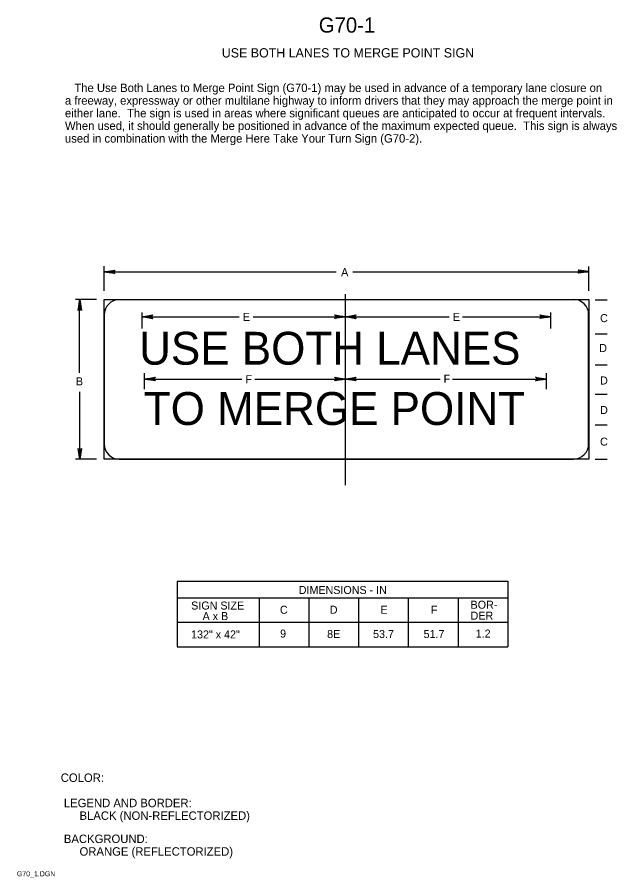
# Model space of a CAD drawing. Extents: x 0.012 to 0.19, y 0.004 to 0.259.
import ezdxf

# ---------------------------------------------------------------- set-up
doc = ezdxf.new("R2010")
doc.units = 0
doc.layers.add('1', color=7, linetype='Continuous')
doc.layers.add('3', color=7, linetype='Continuous')

msp = doc.modelspace()

# ---------------------------------------------------------------- linework, layer by layer
at = {"layer": '1'}
for p, q in [((0.03787, 0.178), (0.03787, 0.18538)), ((0.1815, 0.178), (0.1815, 0.18525)), ((0.03787, 0.18363), (0.10664, 0.18363)), ((0.11156, 0.18365), (0.1815, 0.18365)), ((0.10938, 0.12037), (0.10938, 0.177)), ((0.03563, 0.1755), (0.02938, 0.1755)), ((0.03059, 0.15376), (0.03059, 0.17541)), ((0.03787, 0.12812), (0.03787, 0.1755)), ((0.03787, 0.1755), (0.1815, 0.1755)), ((0.1815, 0.1755), (0.1815, 0.12812)), ((0.18338, 0.17538), (0.187, 0.17538)), ((0.04913, 0.16687), (0.04913, 0.17162)), ((0.10938, 0.16687), (0.10938, 0.17162)), ((0.17025, 0.16687), (0.17025, 0.17162)), ((0.04913, 0.17035), (0.07787, 0.17035)), ((0.082, 0.17037), (0.10938, 0.17037)), ((0.10938, 0.17037), (0.14012, 0.17037)), ((0.14407, 0.17035), (0.17025, 0.17035)), ((0.18338, 0.16525), (0.187, 0.16525)), ((0.18338, 0.15613), (0.187, 0.15613)), ((0.04988, 0.14888), (0.04988, 0.15363)), ((0.10938, 0.14888), (0.10938, 0.15363)), ((0.169, 0.14888), (0.169, 0.15363)), ((0.04988, 0.15187), (0.07867, 0.15187)), ((0.0825, 0.15188), (0.10938, 0.15188)), ((0.10938, 0.15188), (0.1375, 0.15188)), ((0.14118, 0.15187), (0.169, 0.15187)), ((0.03058, 0.14807), (0.03058, 0.12826)), ((0.18338, 0.14738), (0.187, 0.14738)), ((0.18338, 0.13825), (0.187, 0.13825)), ((0.03563, 0.12812), (0.02938, 0.12812)), ((0.1815, 0.12812), (0.03787, 0.12812)), ((0.18338, 0.12812), (0.187, 0.12812))]:
    msp.add_line(p, q, dxfattribs=at)
for points in [[(0.04088, 0.18325), (0.04075, 0.18338), (0.03787, 0.18363), (0.04088, 0.18325), (0.041, 0.18313), (0.03787, 0.18363), (0.04075, 0.18375), (0.04088, 0.18388), (0.03787, 0.18363), (0.041, 0.18413), (0.04088, 0.18388)], [(0.1785, 0.18413), (0.17863, 0.18388), (0.1815, 0.18375), (0.1785, 0.18413), (0.17838, 0.18425), (0.1815, 0.18375), (0.17863, 0.1835), (0.1785, 0.18338), (0.1815, 0.18375), (0.17838, 0.18325), (0.1785, 0.18338)], [(0.03025, 0.1725), (0.0305, 0.17263), (0.03062, 0.1755), (0.03025, 0.1725), (0.03012, 0.17225), (0.03062, 0.1755), (0.03075, 0.17263), (0.031, 0.1725), (0.03062, 0.1755), (0.03112, 0.17225), (0.031, 0.1725)], [(0.05212, 0.17), (0.052, 0.17012), (0.04913, 0.17037), (0.05212, 0.17), (0.05225, 0.16975), (0.04913, 0.17037), (0.052, 0.1705), (0.05212, 0.17062), (0.04913, 0.17037), (0.05225, 0.17087), (0.05212, 0.17062)], [(0.10637, 0.17075), (0.1065, 0.1705), (0.10938, 0.17037), (0.10637, 0.17075), (0.10625, 0.17087), (0.10938, 0.17037), (0.1065, 0.17012), (0.10637, 0.17), (0.10938, 0.17037), (0.10625, 0.16987), (0.10637, 0.17)], [(0.11238, 0.17), (0.11225, 0.17012), (0.10938, 0.17037), (0.11238, 0.17), (0.1125, 0.16975), (0.10938, 0.17037), (0.11225, 0.1705), (0.11238, 0.17062), (0.10938, 0.17037), (0.1125, 0.17087), (0.11238, 0.17062)], [(0.16725, 0.17075), (0.16725, 0.1705), (0.17025, 0.17037), (0.16725, 0.17075), (0.167, 0.17087), (0.17025, 0.17037), (0.16725, 0.17012), (0.16725, 0.17), (0.17025, 0.17037), (0.167, 0.16987), (0.16725, 0.17)], [(0.05287, 0.1515), (0.05275, 0.15175), (0.04988, 0.15188), (0.05287, 0.1515), (0.053, 0.15138), (0.04988, 0.15188), (0.05275, 0.152), (0.05287, 0.15225), (0.04988, 0.15188), (0.053, 0.15238), (0.05287, 0.15225)], [(0.10637, 0.15225), (0.1065, 0.152), (0.10938, 0.15188), (0.10637, 0.15225), (0.10625, 0.15238), (0.10938, 0.15188), (0.1065, 0.15175), (0.10637, 0.1515), (0.10938, 0.15188), (0.10625, 0.15138), (0.10637, 0.1515)], [(0.11238, 0.1515), (0.11225, 0.15175), (0.10938, 0.15188), (0.11238, 0.1515), (0.1125, 0.15138), (0.10938, 0.15188), (0.11225, 0.152), (0.11238, 0.15225), (0.10938, 0.15188), (0.1125, 0.15238), (0.11238, 0.15225)], [(0.166, 0.15225), (0.166, 0.152), (0.169, 0.15188), (0.166, 0.15225), (0.16575, 0.15238), (0.169, 0.15188), (0.166, 0.15175), (0.166, 0.1515), (0.169, 0.15188), (0.16575, 0.15138), (0.166, 0.1515)], [(0.031, 0.13112), (0.03075, 0.131), (0.03062, 0.12812), (0.031, 0.13112), (0.03112, 0.13125), (0.03062, 0.12812), (0.0305, 0.131), (0.03025, 0.13112), (0.03062, 0.12812), (0.03012, 0.13125), (0.03025, 0.13112)]]:
    msp.add_lwpolyline(points, dxfattribs=at)
at = {"layer": '3'}
for p, q in [((0.17702, 0.17547), (0.04237, 0.17541)), ((0.0379, 0.17094), (0.0379, 0.13256)), ((0.18149, 0.13262), (0.18149, 0.171)), ((0.04237, 0.12809), (0.17702, 0.12815)), ((0.0595, 0.09189), (0.15754, 0.09189)), ((0.15754, 0.09189), (0.15754, 0.07247)), ((0.0595, 0.09187), (0.0595, 0.0725)), ((0.15754, 0.08689), (0.0595, 0.08689)), ((0.08379, 0.08689), (0.08379, 0.07247)), ((0.0985, 0.08688), (0.0985, 0.0725)), ((0.11325, 0.08688), (0.11325, 0.0725)), ((0.128, 0.08688), (0.128, 0.0725)), ((0.14279, 0.08689), (0.14279, 0.07247)), ((0.0595, 0.07977), (0.15754, 0.07977)), ((0.0595, 0.07247), (0.15754, 0.07247))]:
    msp.add_line(p, q, dxfattribs=at)
for centre, start, end in [((0.04237, 0.17094), 90, 180), ((0.17702, 0.171), 0, 90), ((0.04237, 0.13256), 180, 270), ((0.17702, 0.13262), 270, 0)]:
    msp.add_arc(centre, 0.00447, start, end, dxfattribs=at)

# ---------------------------------------------------------------- texts
at = {"layer": '1'}
for s, height, p in [('G70-1', 0.0045, (0.1015, 0.25462)), ('USE BOTH LANES TO MERGE POINT SIGN', 0.0027503, (0.07275, 0.24725)), ('   The Use Both Lanes to Merge Point Sign (G70-1) may be used in advance of a temporary lane closure on', 0.00249975, (0.02625, 0.237)), ('a freeway, expressway or other multilane highway to inform drivers that they may approach the merge point in', 0.00249975, (0.02625, 0.23325)), ('either lane.  The sign is used in areas where significant queues are anticipated to occur at frequent intervals.', 0.00249975, (0.02625, 0.2295)), ('When used, it should generally be positioned in advance of the maximum expected queue.  This sign is always', 0.00249975, (0.02625, 0.22575)), ('used in combination with the Merge Here Take Your Turn Sign (G70-2).', 0.0024998, (0.02625, 0.222)), ('A', 0.00238, (0.10812, 0.18238)), ('E', 0.00238, (0.079, 0.16912)), ('E', 0.00238, (0.14125, 0.16912)), ('C', 0.00238, (0.18488, 0.16875)), ('USE BOTH LANES', 0.00975, (0.04825, 0.15613)), ('D', 0.00238, (0.18463, 0.15988)), ('B', 0.00238, (0.0295, 0.15)), ('F', 0.00238, (0.07975, 0.15063)), ('F', 0.00238, (0.1385, 0.15075)), ('D', 0.00238, (0.18488, 0.15025)), ('TO MERGE POINT', 0.00975, (0.04963, 0.13825)), ('D', 0.00238, (0.18488, 0.1415)), ('C', 0.00238, (0.18488, 0.13212)), ('COLOR:', 0.0025, (0.025, 0.03238)), (' LEGEND AND BORDER:', 0.0024998, (0.025, 0.02488)), ('      BLACK (NON-REFLECTORIZED)', 0.0024998, (0.025, 0.02113)), (' BACKGROUND:', 0.0024998, (0.025, 0.01425)), ('      ORANGE (REFLECTORIZED)', 0.0024998, (0.025, 0.0105)), ('G70_1.DGN', 0.0015, (0.012, 0.00438))]:
    msp.add_text(s, height=height, dxfattribs=at).set_placement(p)
at = {"layer": '3'}
for s, height, p in [('DIMENSIONS - IN', 0.0023752, (0.09556, 0.08812)), ('SIGN SIZE', 0.002375, (0.06367, 0.0835)), ('C', 0.00238, (0.08998, 0.08225)), ('D', 0.00238, (0.10475, 0.08225)), ('E', 0.00238, (0.11975, 0.08225)), ('F', 0.00238, (0.13474, 0.08225)), ('BOR-', 0.002375, (0.1465, 0.08375)), ('A x B', 0.002375, (0.06705, 0.08038)), ('DER', 0.002375, (0.1465, 0.0805)), ('132" x 42"', 0.002375, (0.06364, 0.07494)), ('9', 0.00238, (0.09003, 0.07519)), ('8E', 0.002375, (0.10397, 0.07506)), ('53.7', 0.002375, (0.11759, 0.07506)), ('51.7', 0.002375, (0.13256, 0.07506)), ('1.2', 0.002375, (0.14801, 0.07519))]:
    msp.add_text(s, height=height, dxfattribs=at).set_placement(p)

doc.saveas('drawing.dxf')
